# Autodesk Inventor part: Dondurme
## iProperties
Company: Autodesk, Inc.
Shininess: 64.0
Length Units: 11269
Angle Units: 11279
Time Units: 11290
Mass Units: 11283
Length Display Precision: 3
Angle Display Precision: 2
Compacted: True
Part Number: Dondurme
Document SubType Name: Modeling
Created: 2003-11
Catalog Web Link: www.autodesk.com
Vendor: Autodesk, Inc.
Designer: Administrator
Manufacturer: Standard
Standards Organization: Custom
Density: 1 g/cm^3
Density: 0.0
Volumn: 0.0
Area: 0.0
PropertySet Name: Model Information
Control State: 0
Master: False
Checked Out: False
Author: Administrator
